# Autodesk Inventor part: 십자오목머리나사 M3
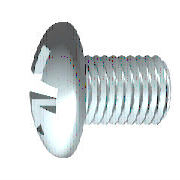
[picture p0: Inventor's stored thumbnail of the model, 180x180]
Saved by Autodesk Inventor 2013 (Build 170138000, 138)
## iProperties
Created: 2012-02
Part Number: 십자오목머리나사 M3
Material: 강철, 연강
Description: 십자 오목 머리 나사
Document SubType Name: Modeling
Standard: KS B 1023
Designer: mduedu
Standards Organization: KS
Language: ko-KR
Size Designation: A  M 3 x 6 - H
Categories: <MemberInstance><Categories><Category DisplayName="조임쇠" InternalName="e4da775c-781d-43d5-af7c-5136215cf5a6" Mnemonic="FSTN"><Category DisplayName="볼트" InternalN
Density: 1 g/cm^3
IsCustomPart: 0
Author: mduedu
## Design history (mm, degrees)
body "Solid1"
workplane "Work Plane3"
sketch "스케치2"
  geometry: L1 (-3.72, 0)-(3.72, 0) reference; L2 (0, -3.72)-(0, 3.72) reference; L3 (0, 1.5)-(0, 0); L4 (0, 0)-(1.5, 0); L5 (0, 0)-(1.879, 1.879); L6 (0.253, 1.479)-(0.261, 0.456); L7 (1.479, 0.253)-(0.456, 0.261); L8 (0.253, -1.479)-(0.261, -0.456); L9 (1.479, -0.253)-(0.456, -0.261); L10 (-0.253, 1.479)-(-0.261, 0.456); L11 (-1.479, 0.253)-(-0.456, 0.261); L12 (-1.479, -0.253)-(-0.456, -0.261); L13 (-0.253, -1.479)-(-0.261, -0.456); A1 r 0.45 centre (0, 0) between (0.45, 0) and (0, 0.45); A2 r 1.5 centre (0, 0) between (1.5, 0) and (1.479, 0.253); A3 r 1.5 centre (0, 0) between (0.253, 1.479) and (0, 1.5); A4 r 1.5 centre (0, 0) between (1.479, 0.253) and (0.253, 1.479); A5 r 1.5 centre (0, 0) between (0, -1.5) and (0.253, -1.479); A6 r 1.5 centre (0, 0) between (0.253, -1.479) and (1.479, -0.253); A7 r 1.5 centre (0, 0) between (1.479, -0.253) and (1.5, 0); A8 r 1.5 centre (0, 0) between (-1.479, 0.253) and (-1.5, 0); A9 r 1.5 centre (0, 0) between (-0.253, 1.479) and (-1.479, 0.253); A10 r 1.5 centre (0, 0) between (0, 1.5) and (-0.253, 1.479); A11 r 1.5 centre (0, 0) between (-1.5, 0) and (-1.479, -0.253); A12 r 1.5 centre (0, 0) between (-1.479, -0.253) and (-0.253, -1.479); A13 r 1.5 centre (0, 0) between (-0.253, -1.479) and (0, -1.5); A14 r 0.525 centre (0, 0) between (0.525, 0) and (0, 0.525); A15 r 0.197 centre (0.457, 0.457) between (0.261, 0.456) and (0.456, 0.261); A16 r 0.197 centre (0.457, -0.457) between (0.456, -0.261) and (0.261, -0.456); A17 r 0.197 centre (-0.457, 0.457) between (-0.456, 0.261) and (-0.261, 0.456); A18 r 0.197 centre (-0.457, -0.457) between (-0.261, -0.456) and (-0.456, -0.261); 1 further point
  constraints: 38 point on circle, 22 end point, 19 symmetric about line, 18 centre point, 4 coincident, 3 collinear, 3 point on line, 3 tangent, 1 perpendicular, 21 other
  dimensions: "d4" = 45 deg angle of L5 L4; "d5" = 0.9 diameter of A1 (= 0.3 x SDM); "d6" = 3 diameter of A4 (= SDM); "d7" = 0.2525 distance from line of L6.start L3 (= 0.5 x SBR); "d14" = 1.05 diameter of A14 (= 0.35 x SDM)
extrude "슬롯" join sketch "스케치2" taper "d15" = 5 deg; stored distance "d54" = 10
revolve "절단부" stored, may be unused: angle "d56" = 90 deg
revolve "본체" stored, may be unused: angle "d18" = 90 deg
workplane "Work Plane1"
sketch "스케치1"
  geometry: L1 (6, 0)-(6, 1.5); L2 (6, 1.5)-(1, 1.5); L3 (3.962, 5.08)-(3.962, 5.08); L4 (-2.4, 0)-(-2.4, 2.59); L5 (-2.2, 1.4)-(-1.036, 0.82); L6 (-1.036, 0.82)-(-0.6, 0); L7 (-0.6, 0)-(6, 0); L8 (-4.305, 0)-(7.717, 0) reference; L9 (0, -1.016)-(0, 6.096) reference; L10 (-2.2, 1.4)-(-2.4, 1.5); L11 (-1.636, 2.657)-(-2.4, 2.59); L12 (-1.636, 2.657)-(0, 2.8); L13 (0, 2.8)-(0, 1.347); L14 (0, 1.347)-(0.693, 1.347); L15 (0.693, 1.347)-(1, 1.5); L16 (1, 1.5)-(0, 1.5); A1 r 5 centre (2.6, 0) between (-1.636, 2.657) and (-2.4, 0)
  constraints: 28 end point, 5 point on line, 4 collinear, 4 point on circle, 3 parallel, 2 perpendicular, 1 centre point, 1 horizontal, 1 tangent
  dimensions: "d1" = 3 diameter of L2 L7 (= GD); "d2" = 1.8 distance from line of L6.end L4 (= STI); "d11" = 3 diameter of L10.end L7 (= SDM); "d12" = 62 deg angle of L6 L7; "d13" = 26.5 deg angle of L5 L7; "d17" = 5.6 diameter of L12.end L7 (= KOD); "d19" = 5 deg angle of L12 L7 (= KEWI); "d20" = 2.4 distance between parallel lines of L4 L13 (= KOH); "d21" = 5 radius of A1 (= KR); "d23" = 2.6935 diameter of L14 L7 (= BDM); "d24" = 5 distance of L1.end L2.end (= GEL); "d25" = 0.30673 horizontal distance of L14.end L2.end (= GAL); "d28" = 6 distance between parallel lines of L1 L13 (= NLG)
fillet "모깎기1" dims "d29" = 1.2 (= RR)
fillet "모깎기2" dims "d16" = 0.101 (= 0.2 x SBR)
feature "스레드" dims "d8" = 5 (= GEL), "d9" = 0
chamfer "모따기1" distance "d26" = 0.30673 (= -0.5 x SPD + 0.5 x GD); stored, may be unused: second distance "d27" = 0.30683 (computed from GUL), angle "d78" = 45 deg
other parameters: "GD" = 3 (= NND) [user parameter; used in 2 equation terms], "NLG" = 6 [user parameter; used in 1 equation term], "GEL" = 5 [user parameter; used in 2 equation terms], "KOD" = 5.6 [user parameter; used in 1 equation term], "KOH" = 2.4 [user parameter; used in 2 equation terms], "SDM" = 3 [user parameter; used in 4 equation terms], "STI" = 1.8 [user parameter; used in 1 equation term], "SBR" = 0.505 [user parameter; used in 2 equation terms], "GAL" = 0.30673 (= 0.61345 x PTC) [user parameter; used in 1 equation term], "SPD" = 2.38655 (= NND - 1.2269 x PTC) [user parameter; used in 1 equation term], "KEWI" = 5 deg [user parameter; used in 1 equation term], "d3" = -2.4 (= -KOH), "d10" = 0, "KR" = 5 [user parameter; used in 1 equation term], "BDM" = 2.6935 [user parameter; used in 1 equation term], "GUL" = 0.30673 (= 0.61345 x PTC) [user parameter; used in 1 equation term], "RR" = 1.2 [user parameter; used in 1 equation term], "d79" = 0, "d80" = 0, "PTC" = 0.5 [user parameter; used in 5 equation terms], "THREADDIA" = 3 [user parameter; used in 1 equation term], "TOA" = 30 deg [user parameter], "NND" = 3 [user parameter; used in 2 equation terms], "GD1" = 2.38655 (= THREADDIA - 1.2269 x PTC) [user parameter]
